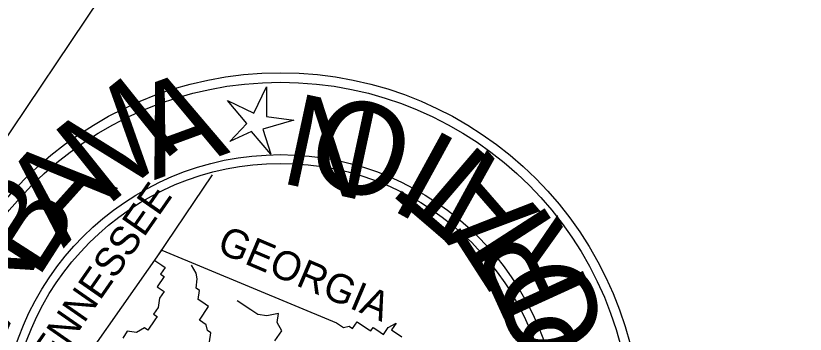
# Model space of a CAD drawing. Extents: x 1797784 to 1799645, y 248583 to 250607.
# Drawn here: x 1799156.4 to 1799206.7, y 249387 to 249407.2 of the extents above; entities that cross this region are included whole.
import ezdxf

# ---------------------------------------------------------------- set-up
doc = ezdxf.new("R2010")
doc.units = 0
doc.layers.add('great seal', color=7, linetype='Continuous')
doc.layers.add('SHT-BDR', color=7, linetype='Continuous')

msp = doc.modelspace()

# ---------------------------------------------------------------- linework, layer by layer
at = {"layer": 'great seal'}
msp.add_line((1799165.427, 249391.872), (1799168.942, 249397.107), dxfattribs=at)
msp.add_line((1799165.427, 249391.872), (1799168.942, 249397.107), dxfattribs=at)
msp.add_line((1799165.427, 249391.872), (1799168.942, 249397.107), dxfattribs=at)
msp.add_lwpolyline([(1799169.905, 249401.841), (1799171.578, 249401.034), (1799172.386, 249402.708), (1799172.379, 249400.813), (1799174.128, 249400.589), (1799172.158, 249400.012), (1799172.663, 249398.407), (1799171.429, 249399.869), (1799170.042, 249399.217), (1799171.139, 249400.38)], close=True, dxfattribs=at)
msp.add_lwpolyline([(1799169.905, 249401.841), (1799171.578, 249401.034), (1799172.386, 249402.708), (1799172.379, 249400.813), (1799174.128, 249400.589), (1799172.158, 249400.012), (1799172.663, 249398.407), (1799171.429, 249399.869), (1799170.042, 249399.217), (1799171.139, 249400.38)], close=True, dxfattribs=at)
msp.add_lwpolyline([(1799169.905, 249401.841), (1799171.578, 249401.034), (1799172.386, 249402.708), (1799172.379, 249400.813), (1799174.128, 249400.589), (1799172.158, 249400.012), (1799172.663, 249398.407), (1799171.429, 249399.869), (1799170.042, 249399.217), (1799171.139, 249400.38)], close=True, dxfattribs=at)
for points in [[(1799158.764, 249382.419), (1799165.72, 249392.308), (1799176.855, 249387.68), (1799177.291, 249387.387), (1799177.656, 249387.459), (1799177.874, 249387.313), (1799177.874, 249387.313), (1799178.167, 249387.749), (1799178.821, 249387.309), (1799179.039, 249387.163), (1799179.186, 249387.381), (1799179.404, 249387.235), (1799179.404, 249387.235), (1799179.622, 249387.088), (1799179.84, 249386.942), (1799180.133, 249387.378), (1799180.644, 249387.668), (1799180.351, 249387.232), (1799181.006, 249386.792)], [(1799158.764, 249382.419), (1799165.72, 249392.308), (1799176.855, 249387.68), (1799177.291, 249387.387), (1799177.656, 249387.459), (1799177.874, 249387.313), (1799177.874, 249387.313), (1799178.167, 249387.749), (1799178.821, 249387.309), (1799179.039, 249387.163), (1799179.186, 249387.381), (1799179.404, 249387.235), (1799179.404, 249387.235), (1799179.622, 249387.088), (1799179.84, 249386.942), (1799180.133, 249387.378), (1799180.644, 249387.668), (1799180.351, 249387.232), (1799181.006, 249386.792)], [(1799158.764, 249382.419), (1799165.72, 249392.308), (1799176.855, 249387.68), (1799177.291, 249387.387), (1799177.656, 249387.459), (1799177.874, 249387.313), (1799177.874, 249387.313), (1799178.167, 249387.749), (1799178.821, 249387.309), (1799179.039, 249387.163), (1799179.186, 249387.381), (1799179.404, 249387.235), (1799179.404, 249387.235), (1799179.622, 249387.088), (1799179.84, 249386.942), (1799180.133, 249387.378), (1799180.644, 249387.668), (1799180.351, 249387.232), (1799181.006, 249386.792)], [(1799165.28, 249391.654), (1799165.28, 249391.654), (1799165.28, 249391.654), (1799165.717, 249391.361), (1799165.935, 249391.214), (1799165.935, 249391.214), (1799165.642, 249390.778), (1799165.642, 249390.778), (1799165.86, 249390.631), (1799165.42, 249389.977), (1799165.857, 249389.684), (1799165.564, 249389.248), (1799165.489, 249388.665), (1799165.343, 249388.447), (1799165.196, 249388.229), (1799165.414, 249388.082), (1799165.268, 249387.864), (1799165.268, 249387.864), (1799164.828, 249387.21), (1799164.828, 249387.21), (1799164.61, 249387.356), (1799164.099, 249387.066), (1799163.516, 249387.141), (1799163.516, 249387.141), (1799163.223, 249386.705)], [(1799165.28, 249391.654), (1799165.28, 249391.654), (1799165.28, 249391.654), (1799165.717, 249391.361), (1799165.935, 249391.214), (1799165.935, 249391.214), (1799165.642, 249390.778), (1799165.642, 249390.778), (1799165.86, 249390.631), (1799165.42, 249389.977), (1799165.857, 249389.684), (1799165.564, 249389.248), (1799165.489, 249388.665), (1799165.343, 249388.447), (1799165.196, 249388.229), (1799165.414, 249388.082), (1799165.268, 249387.864), (1799165.268, 249387.864), (1799164.828, 249387.21), (1799164.828, 249387.21), (1799164.61, 249387.356), (1799164.099, 249387.066), (1799163.516, 249387.141), (1799163.516, 249387.141), (1799163.223, 249386.705)], [(1799165.28, 249391.654), (1799165.28, 249391.654), (1799165.28, 249391.654), (1799165.717, 249391.361), (1799165.935, 249391.214), (1799165.935, 249391.214), (1799165.642, 249390.778), (1799165.642, 249390.778), (1799165.86, 249390.631), (1799165.42, 249389.977), (1799165.857, 249389.684), (1799165.564, 249389.248), (1799165.489, 249388.665), (1799165.343, 249388.447), (1799165.196, 249388.229), (1799165.414, 249388.082), (1799165.268, 249387.864), (1799165.268, 249387.864), (1799164.828, 249387.21), (1799164.828, 249387.21), (1799164.61, 249387.356), (1799164.099, 249387.066), (1799163.516, 249387.141), (1799163.516, 249387.141), (1799163.223, 249386.705)], [(1799168.761, 249386.468), (1799168.836, 249387.051), (1799168.618, 249387.197), (1799168.546, 249387.562), (1799168.11, 249387.855), (1799168.696, 249388.727), (1799168.26, 249389.02), (1799168.041, 249389.167), (1799168.116, 249389.75), (1799167.898, 249389.896), (1799167.973, 249390.479), (1799167.901, 249390.843), (1799167.611, 249391.354)], [(1799168.761, 249386.468), (1799168.836, 249387.051), (1799168.618, 249387.197), (1799168.546, 249387.562), (1799168.11, 249387.855), (1799168.696, 249388.727), (1799168.26, 249389.02), (1799168.041, 249389.167), (1799168.116, 249389.75), (1799167.898, 249389.896), (1799167.973, 249390.479), (1799167.901, 249390.843), (1799167.611, 249391.354)], [(1799168.761, 249386.468), (1799168.836, 249387.051), (1799168.618, 249387.197), (1799168.546, 249387.562), (1799168.11, 249387.855), (1799168.696, 249388.727), (1799168.26, 249389.02), (1799168.041, 249389.167), (1799168.116, 249389.75), (1799167.898, 249389.896), (1799167.973, 249390.479), (1799167.901, 249390.843), (1799167.611, 249391.354)], [(1799172.916, 249386.527), (1799173.355, 249387.182), (1799173.065, 249387.693), (1799173.14, 249388.275), (1799172.411, 249388.132), (1799172.411, 249388.132), (1799171.828, 249388.207), (1799171.392, 249388.5), (1799170.519, 249389.086)], [(1799172.916, 249386.527), (1799173.355, 249387.182), (1799173.065, 249387.693), (1799173.14, 249388.275), (1799172.411, 249388.132), (1799172.411, 249388.132), (1799171.828, 249388.207), (1799171.392, 249388.5), (1799170.519, 249389.086)], [(1799172.916, 249386.527), (1799173.355, 249387.182), (1799173.065, 249387.693), (1799173.14, 249388.275), (1799172.411, 249388.132), (1799172.411, 249388.132), (1799171.828, 249388.207), (1799171.392, 249388.5), (1799170.519, 249389.086)]]:
    msp.add_lwpolyline(points, dxfattribs=at)
for radius in [22.994, 22.994, 22.994, 22.389, 22.389, 22.389, 17.779, 17.779, 17.779, 17.222, 17.222, 17.222]:
    msp.add_circle((1799173.278, 249380.608), radius, dxfattribs=at)
at = {"layer": 'SHT-BDR'}
msp.add_lwpolyline([(1798705.081, 248728.135), (1799541.219, 249973.479), (1798752.501, 250503.033), (1797916.363, 249257.689)], close=True, dxfattribs=at)

# ---------------------------------------------------------------- texts
at = {"layer": 'great seal'}
for s, height, rotation, p in [('M', 5.851, 38.7142, (1799162.157, 249395.016)), ('A', 5.848, 20.1108, (1799165.224, 249396.755)), ('A', 5.848, 20.1108, (1799165.224, 249396.755)), ('A', 5.848, 20.1108, (1799165.224, 249396.755)), ('N', 5.851, 167.8431, (1799179.887, 249401.153)), ('N', 5.851, 167.8431, (1799179.887, 249401.153)), ('N', 5.851, 167.8431, (1799179.887, 249401.153)), ('O', 5.851, 159.5547, (1799182.29, 249400.489)), ('O', 5.851, 159.5547, (1799182.29, 249400.489)), ('O', 5.851, 159.5547, (1799182.29, 249400.489)), ('I', 5.851, 151.2663, (1799184.836, 249399.096)), ('I', 5.851, 151.2663, (1799184.836, 249399.096)), ('I', 5.851, 151.2663, (1799184.836, 249399.096)), ('T', 5.851, 139.3787, (1799187.89, 249397.045)), ('T', 5.851, 139.3787, (1799187.89, 249397.045)), ('T', 5.851, 139.3787, (1799187.89, 249397.045)), ('A', 5.851, 131.0903, (1799189.85, 249394.78)), ('A', 5.851, 131.0903, (1799189.85, 249394.78)), ('A', 5.851, 131.0903, (1799189.85, 249394.78)), ('A', 5.848, 48.0159, (1799159.452, 249392.402)), ('A', 5.848, 48.0159, (1799159.452, 249392.402)), ('A', 5.848, 48.0159, (1799159.452, 249392.402)), ('B', 5.848, 57.3176, (1799157.77, 249390.366)), ('B', 5.848, 57.3176, (1799157.77, 249390.366)), ('B', 5.848, 57.3176, (1799157.77, 249390.366)), ('TENNESSEE', 1.8304, 55.1631, (1799157.966, 249383.588)), ('TENNESSEE', 1.8304, 55.1631, (1799157.966, 249383.588)), ('TENNESSEE', 1.8304, 55.1631, (1799157.966, 249383.588)), ('T', 5.848, 122.8019, (1799191.592, 249392.661)), ('R', 5.851, 114.5135, (1799193.113, 249389.74)), ('GEORGIA', 1.8446, 337.0518, (1799169.145, 249392.224)), ('GEORGIA', 1.8446, 337.0518, (1799169.145, 249392.224)), ('GEORGIA', 1.8446, 337.0518, (1799169.145, 249392.224)), ('A', 5.851, 66.6193, (1799155.791, 249386.948)), ('A', 5.851, 66.6193, (1799155.791, 249386.948)), ('A', 5.851, 66.6193, (1799155.791, 249386.948)), ('O', 5.851, 106.2251, (1799194.123, 249386.531)), ('O', 5.851, 106.2251, (1799194.123, 249386.531)), ('O', 5.851, 106.2251, (1799194.123, 249386.531)), ('P', 5.851, 97.9367, (1799194.843, 249383.832)), ('P', 5.851, 97.9367, (1799194.843, 249383.832)), ('P', 5.851, 97.9367, (1799194.843, 249383.832))]:
    msp.add_text(s, height=height, rotation=rotation, dxfattribs=at).set_placement(p)

doc.saveas('drawing.dxf')
